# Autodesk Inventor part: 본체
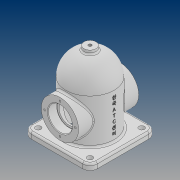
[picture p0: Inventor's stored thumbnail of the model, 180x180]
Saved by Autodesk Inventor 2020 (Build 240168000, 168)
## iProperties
Created: 2021-08
Part Number: 본체
Material: 일반
Document SubType Name: Modeling
Designer: PC312-
Density: 1 g/cm^3
Appearance: 기본값
Mass: 320.706 g
Surface Area: 800.755 cm^2
Volume: 320.706 cm^3
Author: PC312-
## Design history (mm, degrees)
sketch "스케치1"
  geometry: L1 (0, 0)-(124, 0); L2 (0, 0)-(0, -40); L3 (0, -40)-(84, -40); A1 r 40 centre (84, 0) between (84, -40) and (44, 0); 1 further point
  constraints: 6 end point, 2 horizontal, 2 point on circle, 1 centre point, 1 horizontal alignment, 1 point on line, 1 tangent, 1 vertical
  dimensions: "d1" = 124 distance of L1.start L1.end; "d4" = 80 diameter of A1; "d5" = 84 distance from line of L2 A1.centre
revolve "회전1" sketch "스케치1" stored, may be unused: angle "d6" = 90 deg
feature "쉘1" dims "d7" = 8
sketch "스케치2"
  geometry: L1 (-55, 55)-(55, 55); L2 (55, 55)-(55, -55); L3 (55, -55)-(-55, -55); L4 (-55, -55)-(-55, 55); L5 (-55, 55)-(55, -55); L6 (55, 55)-(-55, -55); C1 r 40 at (0, 0) reference; 1 further point
  constraints: 12 end point, 2 midpoint, 2 parallel, 1 horizontal, 1 perpendicular
  dimensions: "d8" = 110 distance of L2.end L3.end; "d9" = 110 distance of L1.end L2.end
extrude "돌출1" join sketch "스케치2" distance "d10" = 10; taper "d11" = 0 deg
node "작업 평면1"
sketch "스케치3"
  geometry: L1 (55, 0)-(-55, 0) reference; C1 r 31 at (0, 48); 2 further points
  constraints: 1 centre point, 1 midpoint, 1 vertical alignment
  dimensions: "d13" = 62 diameter of C1; "d14" = 48 distance from line of L1 C1.centre
extrude "돌출2" join sketch "스케치3" stored distance "d15" = 10; taper "d16" = 0 deg
sketch "스케치4"
  geometry: C1 r 31 at (0, 0) reference; C2 r 20 at (0, 0); 1 further point
  constraints: 1 centre point, 1 coincident
  dimensions: "d17" = 40 diameter of C2
extrude "돌출3" cut sketch "스케치4" distance "d18" = 15; taper "d19" = 0 deg
sketch "스케치5"
  geometry: C1 r 20 at (0, 0) reference; C2 r 16.5 at (0, 0); 1 further point
  constraints: 1 centre point, 1 coincident
  dimensions: "d20" = 33 diameter of C2
extrude "돌출4" cut sketch "스케치5" distance "d21" = 15; taper "d22" = 0 deg
node "작업 평면2"
sketch "스케치6"
  geometry: C1 r 10 at (0, 0); 1 further point
  constraints: 1 centre point, 1 coincident
  dimensions: "d24" = 20 diameter of C1
extrude "돌출5" join sketch "스케치6" stored distance "d25" = 15; taper "d26" = 0 deg
sketch "스케치7"
  geometry: C1 r 10 at (0, 0) reference; 2 further points
  constraints: 1 coincident
hole "구멍1" sketch "스케치7" at (0, 0) diameter "d27" = 5.1881; stored, may be unused: countersink angle "d31" = 90 deg, drill point angle "d33" = 0 deg; dims "d28" = 12, "d29" = 4, "d30" = 2, "d32" = 16
sketch "스케치8"
  geometry: C1 r 31 at (0, 0) reference; 2 further points
  constraints: 1 vertical alignment
  dimensions: "d34" = 25.5 distance of C1.centre point (0, 25.5)
hole "구멍2" sketch "스케치8" at (0, 25.5) diameter "d35" = 3.242; stored, may be unused: countersink angle "d39" = 90 deg, drill point angle "d41" = 118 deg; dims "d36" = 8, "d37" = 4, "d38" = 2, "d40" = 10
fillet "모깎기1" dims "d45" = 12
sketch "스케치9"
  geometry: C1 r 4.5 at (-43, 43); C2 r 4.5 at (-43, -43); C3 r 4.5 at (43, -43); C4 r 4.5 at (43, 43); A1 r 12 centre (-43, 43) between (-43, 55) and (-55, 43) reference; A2 r 12 centre (43, 43) between (55, 43) and (43, 55) reference; A3 r 12 centre (43, -43) between (43, -55) and (55, -43) reference; A4 r 12 centre (-43, -43) between (-55, -43) and (-43, -55) reference; 1 further point
  constraints: 4 centre point, 4 coincident
  dimensions: "d46" = 9 diameter of C1; "d47" = 9 diameter of C2; "d48" = 9 diameter of C3; "d49" = 9 diameter of C4
extrude "돌출6" cut sketch "스케치9" extent not by distance; stored distance "d50" = 0; taper "d51" = 0 deg
node "작업 평면3"
sketch "스케치10"
  geometry: L1 (0, -43)-(0, 43) reference; 3 further points
  constraints: 1 horizontal alignment, 1 midpoint, 1 other
  dimensions: "d53" = 48 distance from line of L1 point (48, 0)
feature "엠보싱1" sketch "스케치10" dims "d5" = 84, "d54" = 0.5, "d55" = 0
chamfer "모따기1" distance "d56" = 1; stored, may be unused: second distance "d57" = 2, angle "d58" = 45 deg
fillet "모깎기2" dims "d59" = 0.3
fillet "모깎기3" dims "d60" = 3
node "솔리드1"
mirror "미러1"
pattern_circular "원형 패턴1" dims angle "d43" = 360 deg
mirror "미러2"
feature "A9D066F2-1C7D-4E18-AEED-F7BC21143FA4" dims "d27" = 5.1881, "d28" = 12, "d29" = 4, "d30" = 2, "d31" = 90 deg, "d32" = 16, "d33" = 0
other parameters: "d23" = 129, "d52" = 77
